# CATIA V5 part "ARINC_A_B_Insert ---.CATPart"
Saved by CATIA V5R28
Part number: ARINC_A_B_INSERT
Revision: ---
Publications: "Logical Termination.1", "Logical Pin.1", "CaCP", "Face_generated(CaCP)", "Axis_generated(CaCP)", "Face_generated(CaCP).1", "BCP", "BCPRPoint_generated(BCP)", "BCPCPlane_generated(BCP)"
Bounding box of the stored display mesh (mm): x 0 to 32.842, y -13.424 to 13.424, z -19.647 to 19.647
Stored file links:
  C:\Users\ajc8720\Documents\BOEING_WORK\0001-2CES\004-AP242\Boeing-Generic_Harness_R3\ARINC_A_B_Insert ---.CATPart
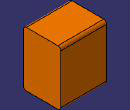
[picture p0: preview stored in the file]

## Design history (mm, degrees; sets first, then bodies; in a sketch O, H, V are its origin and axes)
Parameters
  PartNumber = "BACC66H_A_B_Insert"
  InsertLength = 32.8422 mm
  InsertHeight = 39.2938 mm
  InsertWidth = 26.8478 mm
  EdgeRadius = 2.1082 mm
  PubWorkaround = "DONE"
Set1 "EGFOBody"
  Set2 "CaCPOBody"
    Point1 "CaCPRPoint": (0, 0, 0)
    Plane1 "CaCPCPlane": type OffsetPt, RefPlane yz-plane, RefPoint Point1
  Set3 "BCPOBody"
    Point2 "BCPRPoint": (32.8422 {= InsertLength}, 0, 0)
    Plane2 "BCPCPlane": type OffsetPt, RefPlane yz-plane, RefPoint Point2
Body1 (main body)
  Sketch1 on yz-plane, origin (0, 0, 0), H (0, 1, 0), V (0, 0, 1)
    line L1 (-11.3157, 19.6469) -> (11.3157, 19.6469)
    line L2 (13.4239, 17.5387) -> (13.4239, -17.5387)
    line L3 (11.3157, -19.6469) -> (-11.3157, -19.6469)
    line L4 (-13.4239, -17.5387) -> (-13.4239, 17.5387)
    arc A1 centre (-11.3157, 17.5387) radius 2.1082 from (-13.4239, 17.5387) to (-11.3157, 19.6469) cw
    arc A2 centre (11.3157, 17.5387) radius 2.1082 from (11.3157, 19.6469) to (13.4239, 17.5387) cw
    arc A3 centre (-11.3157, -17.5387) radius 2.1082 from (-13.4239, -17.5387) to (-11.3157, -19.6469) ccw
    arc A4 centre (11.3157, -17.5387) radius 2.1082 from (11.3157, -19.6469) to (13.4239, -17.5387) ccw
    radius A1 = 2.1082 {= EdgeRadius}
    radius A2 = 2.1082 {= EdgeRadius}
    radius A3 = 2.1082 {= EdgeRadius}
    radius A4 = 2.1082 {= EdgeRadius}
    distance L1 L3 = 39.2938 {= InsertHeight}
    distance L2 L4 = 26.8478 {= InsertWidth}
    horizontal: L1 H, L3 H
    vertical: L2 V, L4 V
    symmetry: L1 L3 H, L4 L2 V
    tangency: A1 L4, A1 L1, A2 L1, A2 L2, A3 L4, A3 L3, A4 L3, A4 L2
  Pad1: profile Sketch1, direction (1, 0, 0), length 32.8422 {= InsertLength}
Body2 "Male Cherbourg-CaCP"
  Sketch2 "Sketch.2" on Plane1, origin (0, 0, 0), H (0, 1, 0), V (0, 0, 1)
    line L1 (-0.672, 0.762) -> (0.672, 0.762)
    point P1 (-0.672, 0.762)
    point P2 (0.672, 0.762)
    arc A1 centre (0, 0) radius 1.016 from (-1.016, 0) to (1.016, 0) ccw
    point P3 (0, 0)
    point P4 (-1.016, 0)
    point P5 (1.016, 0)
    reference projected point E1 (0, 0)
    arc A2 centre (0, 0) radius 1.016 from (1.016, 0) to (0.672, 0.762) ccw
    point P6 (0, 0)
    point P7 (1.016, 0)
    point P8 (0.672, 0.762)
    arc A3 centre (0, 0) radius 1.016 from (-0.672, 0.762) to (-1.016, 0) ccw
    point P9 (0, 0)
    point P10 (-0.672, 0.762)
    point P11 (-1.016, 0)
    reference projected point E2 (0, 0)
    reference projected point E3 (0, 0)
    length L1 = 1.344
    radius A1 = 1.016
    radius A3 = 1.016
    radius A2 = 1.016
    distance L1 P5 = 0.762
    distance P4 L1 = 0.762
    distance P7 L1 = 0.762
    distance P11 L1 = 0.762
    coincidence: P3 E1, P6 E2, P9 E3, P8 P2, P10 P1
    horizontal: L1 H
  Pad2: profile Sketch2, direction (1, 0, 0), length 0.508, opposite side up to Plane1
